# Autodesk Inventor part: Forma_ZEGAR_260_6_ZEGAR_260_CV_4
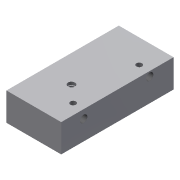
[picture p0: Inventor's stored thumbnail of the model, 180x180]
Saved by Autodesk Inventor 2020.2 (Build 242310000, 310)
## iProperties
Created: 2015-01
Part Number: Forma_ZEGAR_260_6_ZEGAR_260_CV_4
Material: Ogólny
Document SubType Name: Modeling
Designer: F.Stasiak
Density: 1 g/cm^3
Appearance: Domyślna
Catalog Web Link: www.expertbooks.pl
Manager: www.cadconsulting.pl
Company: Fabian Stasiak CAD Consulting
Author: F.Stasiak
Subject: Zbiór ćwiczeń. Autodesk Inventor 2020. Kurs Professional
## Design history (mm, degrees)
node "Forma_ZEGAR_260_4_ZEGAR_260_CV_Base"
feature "Rzeźbienie4"
feature "Gwint1" dims "d0" = 0, "d1" = 0
feature "Rzeźbienie7"
feature "Gwint4" dims "d6" = 0, "d7" = 0
feature "Rzeźbienie9"
feature "Rzeźbienie12"
feature "Bryła1::Forma_ZEGAR_260_4_ZEGAR_260_CV_Base"
tag "Bryła wyprowadzona1"
node "Bryła1"
feature "Forma_ZEGAR_260_4_ZEGAR_260_CV_Base_Bodies"
feature "Powierzchnia4"
body "Srf4"
feature "Powierzchnia7"
body "Srf7"
feature "Powierzchnia9"
body "Srf9"
feature "Powierzchnia12"
body "Srf12"
other parameters: "d10" = 0, "d11" = -26.4075, "d13" = 0, "d14" = -180 deg, "d15" = 0
